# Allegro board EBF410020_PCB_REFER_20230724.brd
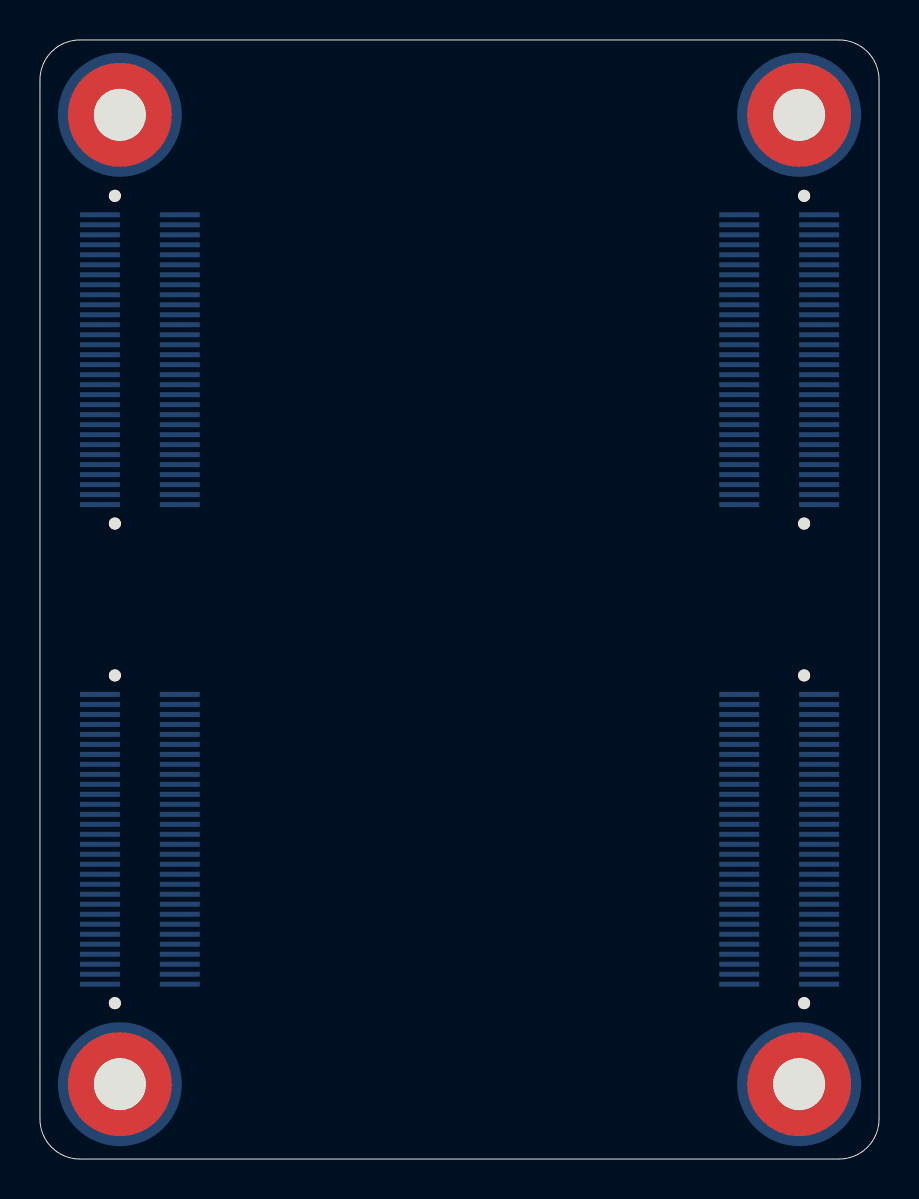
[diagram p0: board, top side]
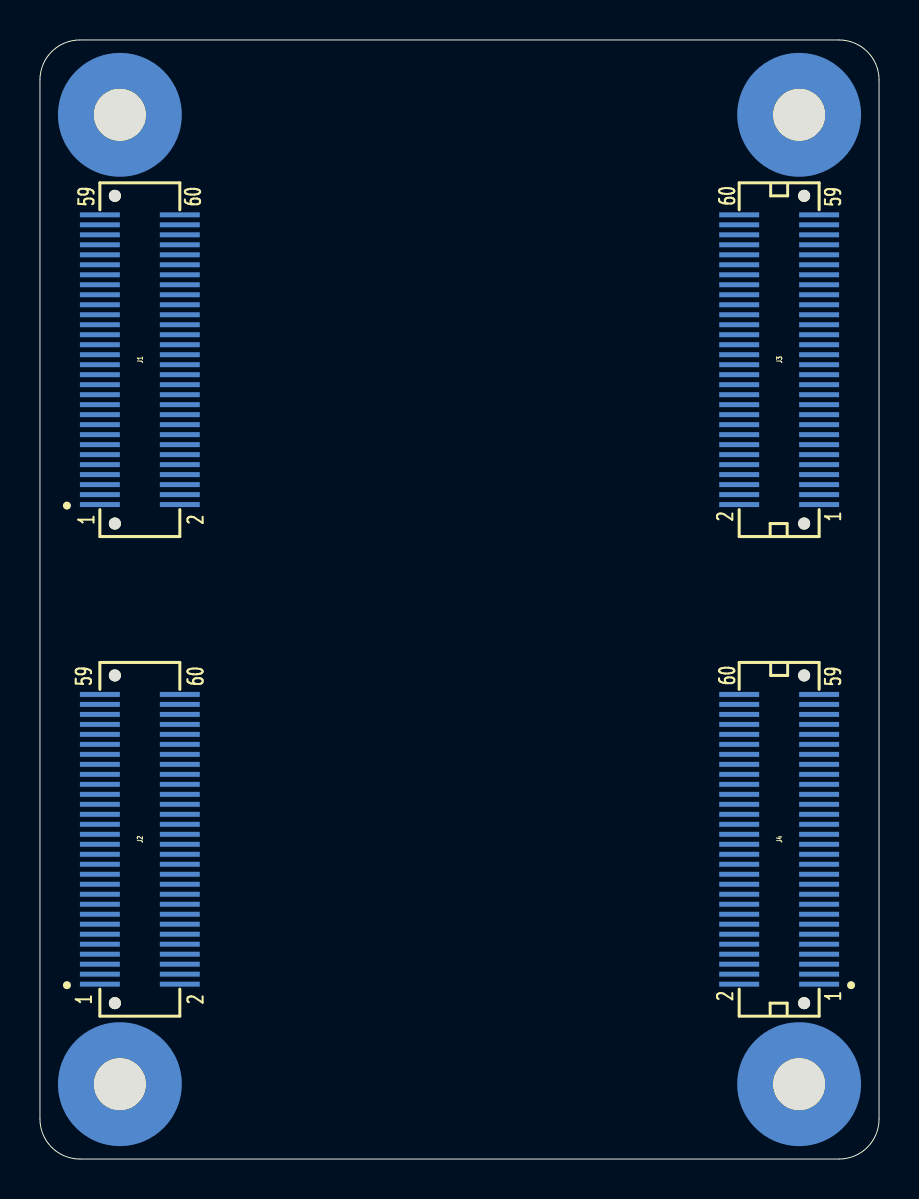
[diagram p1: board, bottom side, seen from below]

Outline 42 x 56 mm; copper layers: TOP, GND02, ART03, ART04, PWR05, ART06, GND07, BOTTOM. Coordinates in mm from the lower left corner of the outline.
Outline path: 0,54 arc(0.59,55.41) 2,56 40,56 arc(41.41,55.41) 42,54 42,2 arc(41.41,0.59) 40,0 2,0 arc(0.59,0.59) 0,2 0,54

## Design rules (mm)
net group BUS-PL-ETH: nets IO35_L12N IO35_L12P
net group C_POW: nets GND VCC_IN
net group DIFF_IO34_L1: nets IO34_L1N IO34_L1P
net group DIFF_IO34_L2: nets IO34_L2N IO34_L2P
net group DIFF_IO34_L3: nets IO34_L3N IO34_L3P
net group DIFF_IO34_L4: nets IO34_L4N IO34_L4P
net group DIFF_IO34_L5: nets IO34_L5N IO34_L5P
net group DIFF_IO34_L6: nets IO34_L6N IO34_L6P
net group DIFF_IO34_L9: nets IO34_L9N IO34_L9P
net group DIFF_IO34_L10: nets IO34_L10N IO34_L10P
net group DIFF_IO34_L11: nets IO34_L11N IO34_L11P
net group DIFF_IO34_L12: nets IO34_L12N IO34_L12P
net group DIFF_IO34_L14: nets IO34_L14N IO34_L14P
net group DIFF_IO34_L18: nets IO34_L18N IO34_L18P
net group DIFF_IO34_L19: nets IO34_L19N IO34_L19P
net group DIFF_IO34_L20: nets IO34_L20N IO34_L20P
net group DIFF_IO34_L21: nets IO34_L21N IO34_L21P
net group DIFF_IO34_L22: nets IO34_L22N IO34_L22P
net group DIFF_IO34_L23: nets IO34_L23N IO34_L23P
net group DIFF_IO34_L24: nets IO34_L24N IO34_L24P
net group DIFF_IO35_L1: nets IO35_L1N IO35_L1P
net group DIFF_IO35_L2: nets IO35_L2N IO35_L2P
net group DIFF_IO35_L3: nets IO35_L3N IO35_L3P
net group DIFF_IO35_L4: nets IO35_L4N IO35_L4P
net group DIFF_IO35_L5: nets IO35_L5N IO35_L5P
net group DIFF_IO35_L6: nets IO35_L6N IO35_L6P
net group DIFF_IO35_L7: nets IO35_L7N IO35_L7P
net group DIFF_IO35_L8: nets IO35_L8N IO35_L8P
net group DIFF_IO35_L9: nets IO35_L9N IO35_L9P
net group DIFF_IO35_L10: nets IO35_L10N IO35_L10P
net group DIFF_IO35_L11: nets IO35_L11N IO35_L11P
net group DIFF_IO35_L13: nets IO35_L13N IO35_L13P
net group DIFF_IO35_L14: nets IO35_L14N IO35_L14P
net group DIFF_IO35_L15: nets IO35_L15N IO35_L15P
net group DIFF_IO35_L16: nets IO35_L16N IO35_L16P
net group DIFF_IO35_L17: nets IO35_L17N IO35_L17P
net group DIFF_IO35_L18: nets IO35_L18N IO35_L18P
net group DIFF_IO35_L19: nets IO35_L19N IO35_L19P
net group DIFF_IO35_L20: nets IO35_L20N IO35_L20P
net group DIFF_IO35_L21: nets IO35_L21N IO35_L21P
net group DIFF_IO35_L22: nets IO35_L22N IO35_L22P
net group DIFF_IO35_L23: nets IO35_L23N IO35_L23P
net group DIFF_IO35_L24: nets IO35_L24N IO35_L24P
net group IO13_L11: nets IO13_L11N IO13_L11P
net group IO13_L12: nets IO13_L12N IO13_L12P
net group IO13_L13: nets IO13_L13N IO13_L13P
net group IO13_L14: nets IO13_L14N IO13_L14P
net group IO13_L15: nets IO13_L15N IO13_L15P
net group IO13_L16: nets IO13_L16N IO13_L16P
net group IO13_L17: nets IO13_L17N IO13_L17P
net group IO13_L18: nets IO13_L18N IO13_L18P
net group IO13_L19: nets IO13_L19N IO13_L19P
net group IO13_L20: nets IO13_L20N IO13_L20P
net group IO13_L21: nets IO13_L21N IO13_L21P
net group IO13_L22: nets IO13_L22N IO13_L22P
net group IO34_L7: nets IO34_L7N IO34_L7P
net group IO34_L8: nets IO34_L8N IO34_L8P
net group IO34_L15: nets IO34_L15N IO34_L15P
net group IO34_L16: nets IO34_L16N IO34_L16P
net group IO34_L17: nets IO34_L17N IO34_L17P
net group XADC_V: nets XADC_VN XADC_VP
net group BUS-BANK13: nets IO13_L6N
net group BUS-LCD: nets IO34_0 IO34_25 IO34_L13N
net group BUS-PS-ETH: nets PS_MIO16 PS_MIO17 PS_MIO18 PS_MIO19 PS_MIO20 PS_MIO21 PS_MIO22 PS_MIO23 PS_MIO24 PS_MIO25 PS_MIO26 PS_MIO27
net group BUS-SD: nets PS_MIO40 PS_MIO41 PS_MIO42 PS_MIO43 PS_MIO44 PS_MIO45
net group BUS-USB: nets PS_MIO28 PS_MIO29 PS_MIO30 PS_MIO31 PS_MIO32 PS_MIO33 PS_MIO34 PS_MIO35 PS_MIO36 PS_MIO37 PS_MIO38 PS_MIO39

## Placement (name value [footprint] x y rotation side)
J1  SGDBF-05-60P-H30  [BTB_2X30_0P5_F]  37 40 270 bottom
J2  SGDBF-05-60P-H30  [BTB_2X30_0P5_F]  37 16 270 bottom
J3  SGDBM-05-60P-H10  [BTB_2X30_0P5_M]  5 40 90 bottom
J4  SGDBM-05-60P-H10  [BTB_2X30_0P5_M]  5 16 90 bottom
SS1  PTH_M2.5  [SMTSO-M2R5-HOLE]  4 3.75 0 top
SS2  PTH_M2.5  [SMTSO-M2R5-HOLE]  38 3.75 0 top
SS3  PTH_M2.5  [SMTSO-M2R5-HOLE]  38 52.25 0 top
SS4  PTH_M2.5  [SMTSO-M2R5-HOLE]  4 52.25 0 top

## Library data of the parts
J1-J4 = 2X30PIN
SS1-SS4 = SPACER

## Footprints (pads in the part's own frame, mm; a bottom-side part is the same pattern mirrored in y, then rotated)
BTB_2X30_0P5_F
  round 0.6 hole 0.6 unplated: (-8.2,-1.25) (8.2,-1.25)
  rect 0.25x2 smd: 1(7.25,-2) 2(7.25,2) 3(6.75,-2) 4(6.75,2) 5(6.25,-2) 6(6.25,2) 7(5.75,-2) 8(5.75,2) 9(5.25,-2) 10(5.25,2) 11(4.75,-2) 12(4.75,2) 13(4.25,-2) 14(4.25,2) 15(3.75,-2) 16(3.75,2) 17(3.25,-2) 18(3.25,2) 19(2.75,-2) 20(2.75,2) 21(2.25,-2) 22(2.25,2) 23(1.75,-2) 24(1.75,2) 25(1.25,-2) 26(1.25,2) 27(0.75,-2) 28(0.75,2) 29(0.25,-2) 30(0.25,2) 31(-0.25,-2) 32(-0.25,2) 33(-0.75,-2) 34(-0.75,2) 35(-1.25,-2) 36(-1.25,2) 37(-1.75,-2) 38(-1.75,2) 39(-2.25,-2) 40(-2.25,2) 41(-2.75,-2) 42(-2.75,2) 43(-3.25,-2) 44(-3.25,2) 45(-3.75,-2) 46(-3.75,2) 47(-4.25,-2) 48(-4.25,2) 49(-4.75,-2) 50(-4.75,2) 51(-5.25,-2) 52(-5.25,2) 53(-5.75,-2) 54(-5.75,2) 55(-6.25,-2) 56(-6.25,2) 57(-6.75,-2) 58(-6.75,2) 59(-7.25,-2) 60(-7.25,2)
BTB_2X30_0P5_M
  round 0.6 hole 0.6 unplated: (-8.2,-1.25) (8.2,-1.25)
  rect 0.25x2 smd: 1(-7.25,-2) 2(-7.25,2) 3(-6.75,-2) 4(-6.75,2) 5(-6.25,-2) 6(-6.25,2) 7(-5.75,-2) 8(-5.75,2) 9(-5.25,-2) 10(-5.25,2) 11(-4.75,-2) 12(-4.75,2) 13(-4.25,-2) 14(-4.25,2) 15(-3.75,-2) 16(-3.75,2) 17(-3.25,-2) 18(-3.25,2) 19(-2.75,-2) 20(-2.75,2) 21(-2.25,-2) 22(-2.25,2) 23(-1.75,-2) 24(-1.75,2) 25(-1.25,-2) 26(-1.25,2) 27(-0.75,-2) 28(-0.75,2) 29(-0.25,-2) 30(-0.25,2) 31(0.25,-2) 32(0.25,2) 33(0.75,-2) 34(0.75,2) 35(1.25,-2) 36(1.25,2) 37(1.75,-2) 38(1.75,2) 39(2.25,-2) 40(2.25,2) 41(2.75,-2) 42(2.75,2) 43(3.25,-2) 44(3.25,2) 45(3.75,-2) 46(3.75,2) 47(4.25,-2) 48(4.25,2) 49(4.75,-2) 50(4.75,2) 51(5.25,-2) 52(5.25,2) 53(5.75,-2) 54(5.75,2) 55(6.25,-2) 56(6.25,2) 57(6.75,-2) 58(6.75,2) 59(7.25,-2) 60(7.25,2)
SMTSO-M2R5-HOLE
  round 5.2 hole 2.6: 1(0,0)

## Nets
GND: J1.1 J1.2 J1.15 J1.20 J1.37 J1.38 J1.43 J1.49 J1.56 J1.59 J1.60 J2.1 J2.2 J2.12 J2.15 J2.16 J2.20 J2.21 J2.24 J2.30 J2.31 J2.36 J2.37 J2.42 J2.43 J2.48 J2.49 J2.54 J2.59 J2.60 J3.1 J3.2 J3.12 J3.15 J3.18 J3.24 J3.25 J3.30 J3.35 J3.40 J3.45 J3.50 J3.59 J3.60 J4.9 J4.10 J4.11 J4.12 J4.13 J4.14 J4.15 J4.16 J4.32 J4.45 J4.59 J4.60 SS1.1(NC_1) SS2.1(NC_1) SS3.1(NC_1) SS4.1(NC_1)
VCC_IN: J4.1 J4.2 J4.3 J4.4 J4.5 J4.6 J4.7 J4.8
BOOT_MIO4: J2.19
BOOT_MIO5: J2.17
FPGA_DONE: J2.22
FPGA_TCK: J2.4
FPGA_TDI: J2.8
FPGA_TDO: J2.6
FPGA_TMS: J2.10
IO13_L6N: J2.14
IO13_L11N: J2.56
IO13_L11P: J2.58
IO13_L12N: J2.50
IO13_L12P: J2.52
IO13_L13N: J2.44
IO13_L13P: J2.46
IO13_L14N: J2.38
IO13_L14P: J2.40
IO13_L15N: J2.32
IO13_L15P: J2.34
IO13_L16N: J2.55
IO13_L16P: J2.57
IO13_L17N: J2.51
IO13_L17P: J2.53
IO13_L18N: J2.45
IO13_L18P: J2.47
IO13_L19N: J2.39
IO13_L19P: J2.41
IO13_L20N: J2.33
IO13_L20P: J2.35
IO13_L21N: J2.27
IO13_L21P: J2.29
IO13_L22N: J2.23
IO13_L22P: J2.25
IO34_0: J1.11
IO34_25: J1.58
IO34_L1N: J1.6
IO34_L1P: J1.4
IO34_L2N: J1.10
IO34_L2P: J1.8
IO34_L3N: J1.14
IO34_L3P: J1.12
IO34_L4N: J1.5
IO34_L4P: J1.3
IO34_L5N: J1.18
IO34_L5P: J1.16
IO34_L6N: J1.36
IO34_L6P: J1.34
IO34_L7N: J1.23
IO34_L7P: J1.21
IO34_L8N: J1.19
IO34_L8P: J1.17
IO34_L9N: J1.28
IO34_L9P: J1.26
IO34_L10N: J1.9
IO34_L10P: J1.7
IO34_L11N: J1.41
IO34_L11P: J1.39
IO34_L12N: J1.54
IO34_L12P: J1.52
IO34_L13N: J1.13
IO34_L14N: J2.3
IO34_L14P: J2.5
IO34_L15N: J1.35
IO34_L15P: J1.33
IO34_L16N: J1.31
IO34_L16P: J1.29
IO34_L17N: J1.27
IO34_L17P: J1.25
IO34_L18N: J1.42
IO34_L18P: J1.40
IO34_L19N: J1.46
IO34_L19P: J1.44
IO34_L20N: J2.7
IO34_L20P: J2.9
IO34_L21N: J1.24
IO34_L21P: J1.22
IO34_L22N: J1.50
IO34_L22P: J1.48
IO34_L23N: J2.11
IO34_L23P: J2.13
IO34_L24N: J1.32
IO34_L24P: J1.30
IO35_IO0: J3.8
IO35_IO25: J3.10
IO35_L1N: J3.56
IO35_L1P: J3.58
IO35_L2N: J3.52
IO35_L2P: J3.54
IO35_L3N: J3.46
IO35_L3P: J3.48
IO35_L4N: J3.42
IO35_L4P: J3.44
IO35_L5N: J3.36
IO35_L5P: J3.38
IO35_L6N: J3.32
IO35_L6P: J3.34
IO35_L7N: J3.55
IO35_L7P: J3.57
IO35_L8N: J3.51
IO35_L8P: J3.53
IO35_L9N: J3.47
IO35_L9P: J3.49
IO35_L10N: J1.47
IO35_L10P: J1.45
IO35_L11N: J3.41
IO35_L11P: J3.43
IO35_L12N: J3.37
IO35_L12P: J3.39
IO35_L13N: J1.53
IO35_L13P: J1.51
IO35_L14N: J1.57
IO35_L14P: J1.55
IO35_L15N: J3.31
IO35_L15P: J3.33
IO35_L16N: J3.27
IO35_L16P: J3.29
IO35_L17N: J3.21
IO35_L17P: J3.23
IO35_L18N: J3.17
IO35_L18P: J3.19
IO35_L19N: J3.26
IO35_L19P: J3.28
IO35_L20N: J3.20
IO35_L20P: J3.22
IO35_L21N: J3.11
IO35_L21P: J3.13
IO35_L22N: J3.7
IO35_L22P: J3.9
IO35_L23N: J3.3
IO35_L23P: J3.5
IO35_L24N: J3.14
IO35_L24P: J3.16
PS_MIO0: J4.17
PS_MIO7: J4.19
PS_MIO8: J4.21
PS_MIO9: J4.23
PS_MIO10: J4.25
PS_MIO11: J4.27
PS_MIO12: J4.30
PS_MIO13: J4.58
PS_MIO14: J4.29
PS_MIO15: J4.31
PS_MIO16: J4.33
PS_MIO17: J4.35
PS_MIO18: J4.37
PS_MIO19: J4.39
PS_MIO20: J4.41
PS_MIO21: J4.43
PS_MIO22: J4.47
PS_MIO23: J4.49
PS_MIO24: J4.51
PS_MIO25: J4.53
PS_MIO26: J4.55
PS_MIO27: J4.57
PS_MIO28: J4.34
PS_MIO29: J4.36
PS_MIO30: J4.38
PS_MIO31: J4.40
PS_MIO32: J4.42
PS_MIO33: J4.44
PS_MIO34: J4.46
PS_MIO35: J4.48
PS_MIO36: J4.50
PS_MIO37: J4.52
PS_MIO38: J4.54
PS_MIO39: J4.56
PS_MIO40: J4.18
PS_MIO41: J4.20
PS_MIO42: J4.22
PS_MIO43: J4.24
PS_MIO44: J4.26
PS_MIO45: J4.28
PS_MIO52: J3.4
PS_MIO53: J3.6
PS_POR_B: J2.18
XADC_VN: J2.26
XADC_VP: J2.28

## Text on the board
User.5: FIGURE | SIZE | 8.0 | 12.0 | 102.362 | 23.622 | DRILL CHART: TOP to BOTTOM | ALL UNITS ARE IN MILS | PLATED | NON-PLATED | QTY | 839 | 193 | 4 | 8
